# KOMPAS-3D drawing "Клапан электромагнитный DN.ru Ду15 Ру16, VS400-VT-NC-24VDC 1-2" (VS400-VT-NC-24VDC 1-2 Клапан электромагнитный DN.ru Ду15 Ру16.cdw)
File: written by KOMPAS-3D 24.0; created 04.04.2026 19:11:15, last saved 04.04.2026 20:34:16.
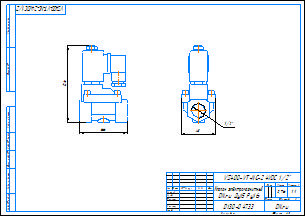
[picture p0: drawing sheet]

Document properties: c3d_UniqueCompID: ef56311e-7521-43dc-8291-0e6108b3d81d; Обозначение: VS400-ET-NC-220VAC 1-2; Наименование: Клапан электромагнитный DN.ru Ду15 Ру16; Автор: artio; Класс точности: c; Знак неуказанной шероховатости: Шероховатость не задана; Рассекать на разрезах: Да; c3d_UniqueCompID: ef56311e-7521-43dc-8291-0e6108b3d81d; Обозначение: VS400-ET-NC-220VAC 3-8; Наименование: Клапан электромагнитный DN.ru Ду10 Ру16; Автор: artio; Класс точности: c; Знак неуказанной шероховатости: Шероховатость не задана; Рассекать на разрезах: Да; Автор: artio; Форматы листов документа: A3; Полное имя файла: VS400-VT-NC-24VDC 1-2 Клапан электромагнитный DN.ru Ду15 Ру16.m3d; Масса: 0.759; Наименование: Клапан электромагнитный DN.ru Ду15 Ру16; Количество листов документа: 1; Примечание: D130-04733

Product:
- Body: Тело 1  | qty 1
    Масса: 1.030062
- Part/product: Клапан электромагнитный DN.ru Ду15 Ру16  | designation VS400-VT-NC-24VDC 1-2
    Масса: 0.759
    Раздел спецификации: Прочие изделия
    Примечание: D130-04733
    additional columns: ef56311e-7521-43dc-8291-0e6108b3d81d; VS400-ET-NC-220VAC 1-2; artio; c; Шероховатость не задана; Да

Views: Вид 1, Спереди, Проекционный вид 2
Referenced files in C:\Users\artio\OneDrive\Рабочий стол\Клапан электромагнитный DN.ru\VS400-ET-NC\VS400-ET-NC-24VDC\: VS400-ET-NC-24VDC 3-8 Клапан электромагнитный DN.ru Ду10 Ру16.m3d
Referenced files in C:\Users\artio\OneDrive\Рабочий стол\Клапан электромагнитный DN.ru\VS400-VT-NC\VS400-VT-NC-24VDC\: VS400-VT-NC-24VDC 1-2 Клапан электромагнитный DN.ru Ду15 Ру16.m3d
Referenced files in C:\Users\artio\OneDrive\Рабочий стол\Клапан электромагнитный DN.ru\VS400-ET-NC\: VS400-ET-NC-24VDC 3-8 Клапан электромагнитный DN.ru Ду10 Ру16.cdw
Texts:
  VS400-VT-NC-24VDC 1-2
  Клапан электромагнитный
  DN.ru Ду15 Ру16
  VS400-VT-NC-24VDC 1/2"
  VS400-VT-NC-24VDC 1/2"-
  Клапан электромагнитный DN.ru Ду15 Ру16
  VS400-VT-NC-24VDC 1-2 Клапан электромагнитный DN.ru Ду15 Ру16
Dimensions and other numbers on the sheet: 0; 3; 2; 4; 48; 1/2"; 66; 106; 1:1; 1; 0,76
